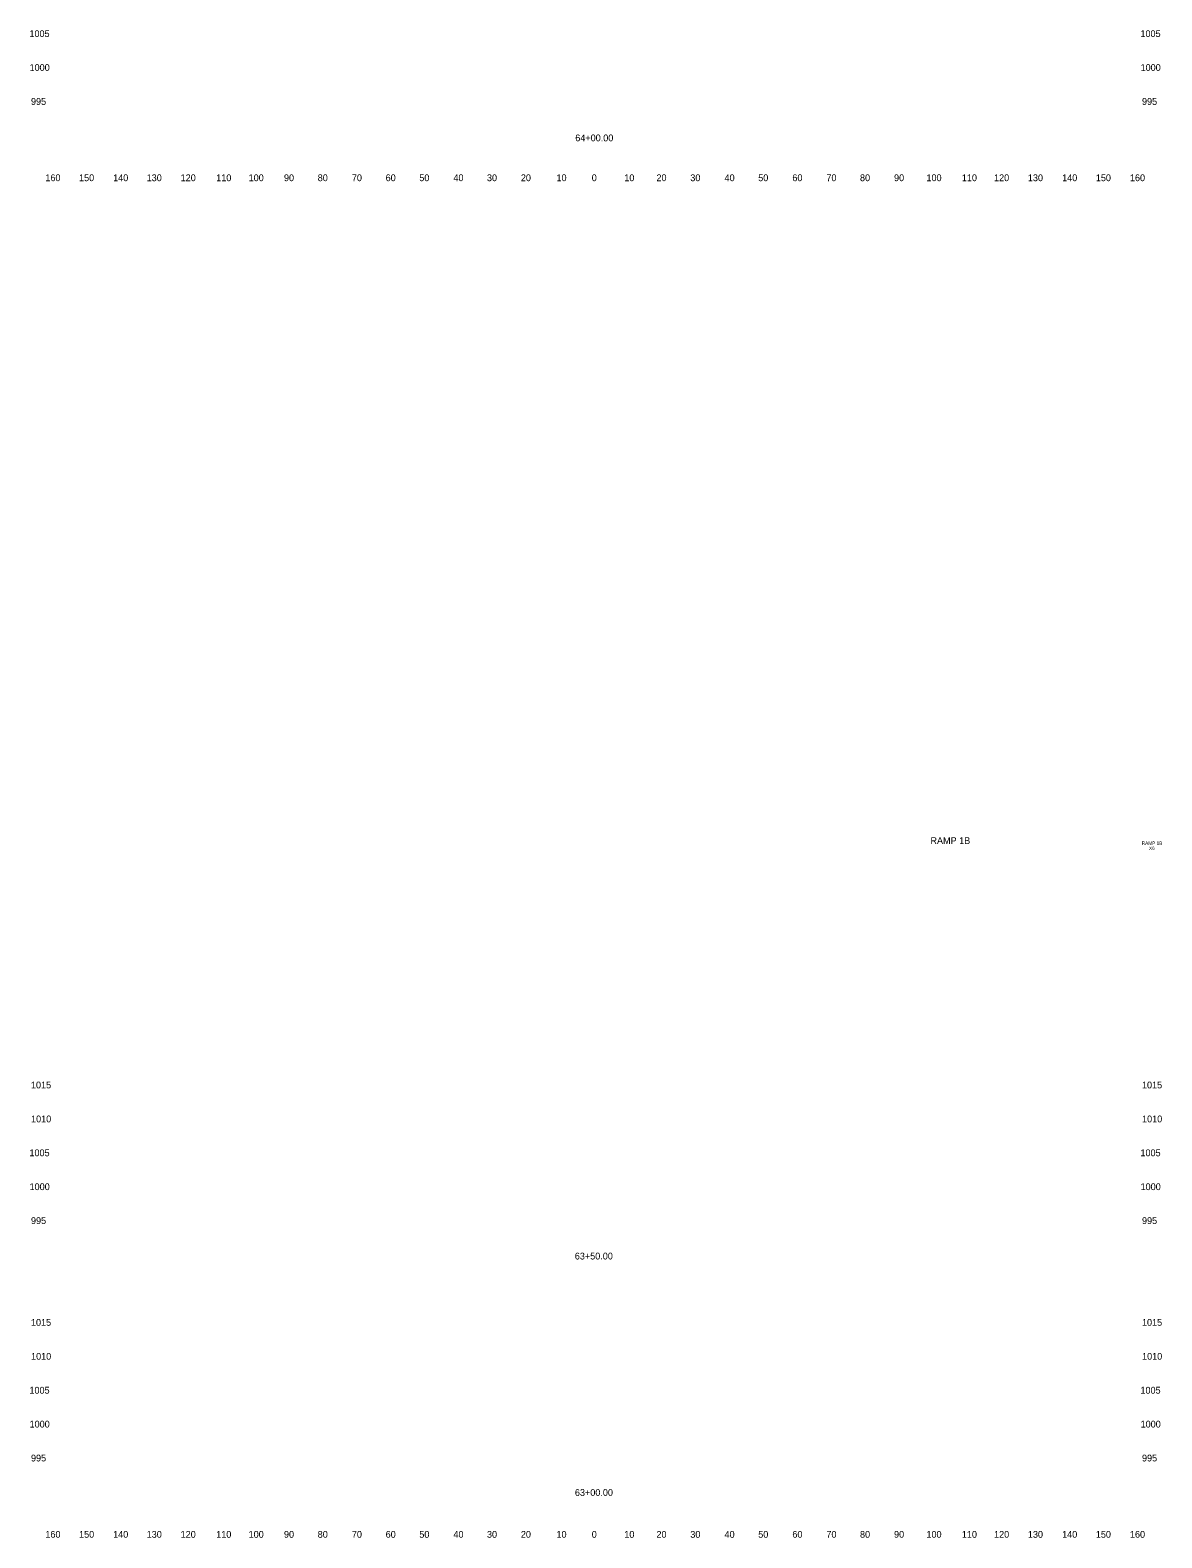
# Model space of a CAD drawing. Extents: x 4994 to 5843, y 4997 to 8804.
# Drawn here: x 4993.6 to 5327.5, y 6997.5 to 7442 of the extents above; entities that cross this region are included whole.
import ezdxf

# ---------------------------------------------------------------- set-up
doc = ezdxf.new("R2010")
doc.units = 0
for name, color, linetype in [('CLS_Search_Dist', 7, 'Continuous'), ('RD_XE_Ground', 7, 'Continuous'), ('UC_PD_Text', 7, 'Continuous')]:
    doc.layers.add(name, color=color, linetype=linetype)

msp = doc.modelspace()

# ---------------------------------------------------------------- texts
at = {"layer": 'CLS_Search_Dist'}
for s, p in [('1005', (4993.4, 7440)), ('1005', (5321.2, 7440)), ('1000', (4993.44, 7430)), ('1000', (5321.24, 7430)), ('995', (4993.86, 7420)), ('995', (5321.66, 7420)), ('160', (4998.1, 7397.5)), ('150', (5008.04, 7397.5)), ('140', (5018.1, 7397.5)), ('130', (5027.99, 7397.5)), ('120', (5038.01, 7397.5)), ('110', (5048.51, 7397.5)), ('100', (5058.07, 7397.5)), ('90', (5068.5, 7397.5)), ('80', (5078.46, 7397.5)), ('70', (5088.54, 7397.5)), ('60', (5098.5, 7397.5)), ('50', (5108.43, 7397.5)), ('40', (5118.5, 7397.5)), ('30', (5128.39, 7397.5)), ('20', (5138.4, 7397.5)), ('10', (5148.91, 7397.5)), ('0', (5159.3, 7397.5)), ('0', (5159.3, 7397.5)), ('10', (5168.91, 7397.5)), ('20', (5178.4, 7397.5)), ('30', (5188.39, 7397.5)), ('40', (5198.5, 7397.5)), ('50', (5208.43, 7397.5)), ('60', (5218.5, 7397.5)), ('70', (5228.54, 7397.5)), ('80', (5238.46, 7397.5)), ('90', (5248.5, 7397.5)), ('100', (5258.07, 7397.5)), ('110', (5268.51, 7397.5)), ('120', (5278.01, 7397.5)), ('130', (5287.99, 7397.5)), ('140', (5298.1, 7397.5)), ('150', (5308.04, 7397.5)), ('160', (5318.1, 7397.5)), ('1015', (4993.85, 7130)), ('1015', (5321.65, 7130)), ('1010', (4993.88, 7120)), ('1010', (5321.68, 7120)), ('1005', (4993.4, 7110)), ('1005', (5321.2, 7110)), ('1000', (4993.44, 7100)), ('1000', (5321.24, 7100)), ('995', (4993.86, 7090)), ('995', (5321.66, 7090)), ('1015', (4993.85, 7060)), ('1015', (5321.65, 7060)), ('1010', (4993.88, 7050)), ('1010', (5321.68, 7050)), ('1005', (4993.4, 7040)), ('1005', (5321.2, 7040)), ('1000', (4993.44, 7030)), ('1000', (5321.24, 7030)), ('995', (4993.86, 7020)), ('995', (5321.66, 7020)), ('160', (4998.1, 6997.5)), ('150', (5008.04, 6997.5)), ('140', (5018.1, 6997.5)), ('130', (5027.99, 6997.5)), ('120', (5038.01, 6997.5)), ('110', (5048.51, 6997.5)), ('100', (5058.07, 6997.5)), ('90', (5068.5, 6997.5)), ('80', (5078.46, 6997.5)), ('70', (5088.54, 6997.5)), ('60', (5098.5, 6997.5)), ('50', (5108.43, 6997.5)), ('40', (5118.5, 6997.5)), ('30', (5128.39, 6997.5)), ('20', (5138.4, 6997.5)), ('10', (5148.91, 6997.5)), ('0', (5159.3, 6997.5)), ('0', (5159.3, 6997.5)), ('10', (5168.91, 6997.5)), ('20', (5178.4, 6997.5)), ('30', (5188.39, 6997.5)), ('40', (5198.5, 6997.5)), ('50', (5208.43, 6997.5)), ('60', (5218.5, 6997.5)), ('70', (5228.54, 6997.5)), ('80', (5238.46, 6997.5)), ('90', (5248.5, 6997.5)), ('100', (5258.07, 6997.5)), ('110', (5268.51, 6997.5)), ('120', (5278.01, 6997.5)), ('130', (5287.99, 6997.5)), ('140', (5298.1, 6997.5)), ('150', (5308.04, 6997.5)), ('160', (5318.1, 6997.5))]:
    msp.add_text(s, height=2, dxfattribs=at).set_placement(p)
at = {"layer": 'RD_XE_Ground'}
for s, p in [('64+00.00', (5154.45, 7409.26)), ('63+50.00', (5154.31, 7079.55)), ('63+00.00', (5154.34, 7009.84))]:
    msp.add_text(s, height=2, dxfattribs=at).set_placement(p)
at = {"layer": 'UC_PD_Text'}
for s, height, p in [('RAMP 1B', 2, (5259.24, 7202.06)), ('RAMP 1B', 1, (5321.59, 7201.8)), ('X6', 1, (5323.71, 7200.3))]:
    msp.add_text(s, height=height, dxfattribs=at).set_placement(p)

doc.saveas('drawing.dxf')
